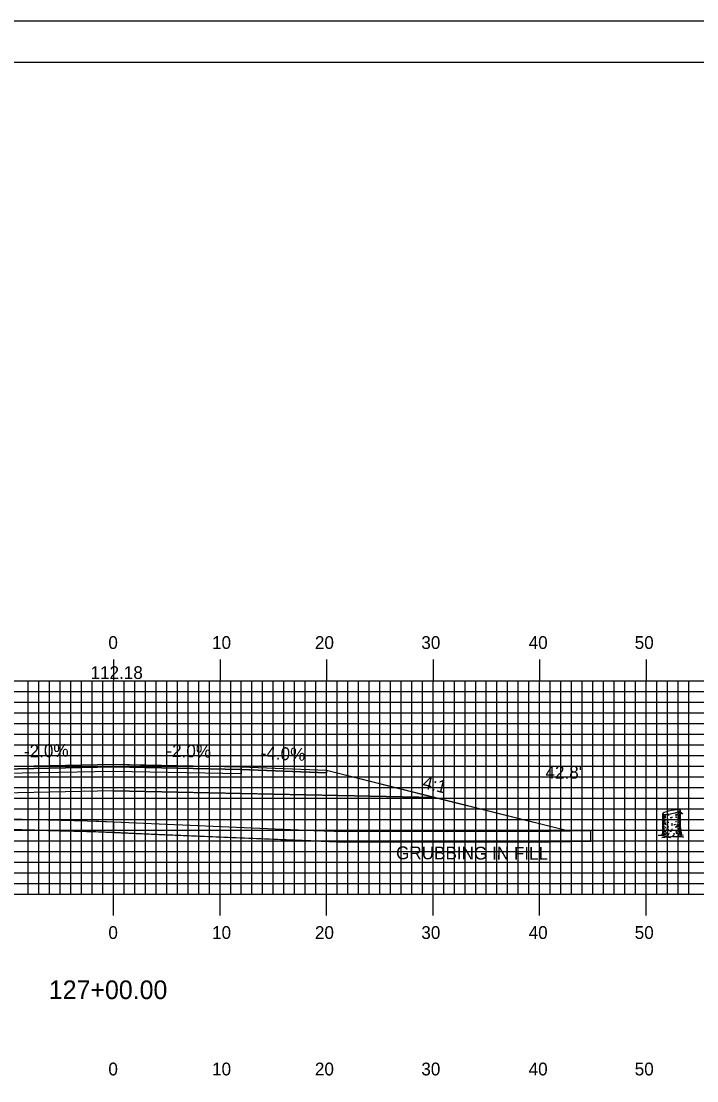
# Model space of a CAD drawing. Extents: x 1773203 to 1773546, y 442591 to 442811.
# Drawn here: x 1773360 to 1773423.4, y 442711.2 to 442810.5 of the extents above; entities that cross this region are included whole.
import ezdxf

# ---------------------------------------------------------------- set-up
doc = ezdxf.new("R2010")
doc.units = 0
for name, color, linetype in [('ANNOTATION', 7, 'Continuous'), ('BORDER', 7, 'Continuous'), ('D_Drainage_Culvert', 7, 'Continuous'), ('D_Roadway_Centerline', 7, 'Continuous'), ('D_Roadway_Centerline_Text', 7, 'Continuous'), ('D_Roadway_Edge_Shoulder', 7, 'Continuous'), ('D_Roadway_Edge_TW', 7, 'Continuous'), ('D_Roadway_Pavement', 7, 'Continuous'), ('D_Roadway_SubGrade', 7, 'Continuous'), ('D_Text_Standard', 7, 'Continuous'), ('GRUBBING IN FILL', 7, 'Continuous'), ('H_V ANNOTATION', 7, 'Continuous'), ('M_Trees_Conifer_Pay', 7, 'Continuous'), ('MAJOR', 7, 'Continuous'), ('MINOR', 7, 'Continuous'), ('PLOT BOUNDARY', 7, 'Continuous'), ('S_Roadway_Centerline', 7, 'Continuous')]:
    doc.layers.add(name, color=color, linetype=linetype)

msp = doc.modelspace()

# ---------------------------------------------------------------- linework, layer by layer
at = {"layer": 'BORDER'}
msp.add_lwpolyline([(1773219.033, 442596.665), (1773539.033, 442596.665), (1773539.033, 442806.665), (1773219.033, 442806.665)], close=True, dxfattribs=at)
at = {"layer": 'D_Drainage_Culvert'}
for p, q in [((1773380.633, 442740.604), (1773388.633, 442740.284)), ((1773368.632, 442738.344), (1773398.809, 442737.74))]:
    msp.add_line(p, q, dxfattribs=at)
msp.add_lwpolyline([(1773388.633, 442740.284), (1773392.633, 442739.284), (1773411.388, 442734.596)], dxfattribs=at)
at = {"layer": 'D_Roadway_Centerline'}
msp.add_lwpolyline([(1773327.807, 442736.112), (1773343.707, 442740.087), (1773348.633, 442740.284), (1773356.633, 442740.604), (1773368.632, 442740.844), (1773371.168, 442740.793), (1773380.633, 442740.604), (1773388.633, 442740.284), (1773388.633, 442740.284), (1773398.809, 442737.74), (1773411.388, 442734.596)], dxfattribs=at)
at = {"layer": 'D_Roadway_Edge_Shoulder'}
msp.add_lwpolyline([(1773380.633, 442740.604), (1773388.633, 442740.284), (1773388.633, 442740.034), (1773380.633, 442740.354)], close=True, dxfattribs=at)
at = {"layer": 'D_Roadway_Edge_TW'}
msp.add_lwpolyline([(1773356.632, 442740.354), (1773356.632, 442740.604), (1773368.632, 442740.844), (1773380.633, 442740.604), (1773380.633, 442740.354), (1773368.632, 442740.594)], close=True, dxfattribs=at)
at = {"layer": 'D_Roadway_Pavement'}
msp.add_lwpolyline([(1773356.632, 442739.937), (1773356.632, 442740.354), (1773368.632, 442740.594), (1773380.633, 442740.354), (1773380.633, 442739.937), (1773368.632, 442740.177)], close=True, dxfattribs=at)
at = {"layer": 'D_Roadway_SubGrade'}
msp.add_lwpolyline([(1773356.632, 442738.104), (1773333.959, 442737.65), (1773343.707, 442740.087), (1773343.707, 442739.829), (1773348.633, 442740.034), (1773356.632, 442740.354), (1773368.632, 442740.594), (1773380.633, 442740.354), (1773388.633, 442740.034), (1773388.633, 442740.034), (1773388.633, 442740.284), (1773398.809, 442737.74), (1773380.633, 442738.104), (1773368.632, 442738.344)], close=True, dxfattribs=at)
at = {"layer": 'GRUBBING IN FILL'}
msp.add_line((1773413.419, 442734.636), (1773413.419, 442733.636), dxfattribs=at)
msp.add_line((1773413.419, 442734.636), (1773413.419, 442733.636), dxfattribs=at)
for points in [[(1773323.846, 442736.25), (1773330.638, 442736.014), (1773339.301, 442735.713), (1773344.935, 442735.692), (1773349.428, 442735.77), (1773353.921, 442735.847), (1773360.04, 442735.698), (1773366.16, 442735.55), (1773368.633, 442735.449), (1773368.633, 442734.448), (1773366.13, 442734.55), (1773360.023, 442734.698), (1773353.917, 442734.846), (1773349.433, 442734.769), (1773343.621, 442734.682), (1773339.276, 442734.714), (1773331.561, 442734.981), (1773323.846, 442735.249)], [(1773323.846, 442736.25), (1773330.638, 442736.014), (1773339.301, 442735.713), (1773344.935, 442735.692), (1773349.428, 442735.77), (1773353.921, 442735.847), (1773360.04, 442735.698), (1773366.16, 442735.55), (1773368.633, 442735.449), (1773368.633, 442734.448), (1773366.13, 442734.55), (1773360.023, 442734.698), (1773353.917, 442734.846), (1773349.433, 442734.769), (1773343.621, 442734.682), (1773339.276, 442734.714), (1773331.561, 442734.981), (1773323.846, 442735.249)], [(1773368.633, 442735.449), (1773372.921, 442735.264), (1773380.188, 442734.957), (1773387.455, 442734.651), (1773388.889, 442734.593), (1773399.956, 442734.547), (1773409.589, 442734.56), (1773413.419, 442734.636), (1773413.419, 442733.636), (1773409.6, 442733.56), (1773399.951, 442733.547), (1773390.302, 442733.534), (1773380.146, 442733.958), (1773371.986, 442734.299), (1773368.633, 442734.448)], [(1773368.633, 442735.449), (1773372.921, 442735.264), (1773380.188, 442734.957), (1773387.455, 442734.651), (1773388.889, 442734.593), (1773399.956, 442734.547), (1773409.589, 442734.56), (1773413.419, 442734.636), (1773413.419, 442733.636), (1773409.6, 442733.56), (1773399.951, 442733.547), (1773390.302, 442733.534), (1773380.146, 442733.958), (1773371.986, 442734.299), (1773368.633, 442734.448)]]:
    msp.add_lwpolyline(points, close=True, dxfattribs=at)
msp.add_lwpolyline([(1773323.846, 442735.249), (1773339.276, 442734.714), (1773342.295, 442734.671), (1773344.948, 442734.693), (1773353.917, 442734.846), (1773366.13, 442734.55), (1773367.217, 442734.51), (1773372.878, 442734.265), (1773387.414, 442733.652), (1773390.302, 442733.534), (1773409.6, 442733.56), (1773413.419, 442733.636)], dxfattribs=at)
msp.add_lwpolyline([(1773323.846, 442735.249), (1773339.276, 442734.714), (1773342.295, 442734.671), (1773344.948, 442734.693), (1773353.917, 442734.846), (1773366.13, 442734.55), (1773367.217, 442734.51), (1773372.878, 442734.265), (1773387.414, 442733.652), (1773390.302, 442733.534), (1773409.6, 442733.56), (1773413.419, 442733.636)], dxfattribs=at)
at = {"layer": 'M_Trees_Conifer_Pay'}
for p, q in [((1773420.188, 442734.48), (1773420.188, 442736.202)), ((1773420.235, 442736.164), (1773420.235, 442735.693)), ((1773420.294, 442736.153), (1773420.294, 442736.055)), ((1773420.294, 442735.981), (1773420.294, 442735.777)), ((1773420.419, 442736.145), (1773420.419, 442735.913)), ((1773420.419, 442735.872), (1773420.419, 442735.798)), ((1773420.639, 442736.166), (1773420.639, 442735.998)), ((1773421.044, 442735.934), (1773421.044, 442735.839)), ((1773421.435, 442736.208), (1773421.435, 442736.008)), ((1773421.435, 442735.95), (1773421.435, 442735.862)), ((1773421.663, 442736.404), (1773421.663, 442736.181)), ((1773421.663, 442736.092), (1773421.663, 442736.045)), ((1773421.72, 442735.909), (1773421.669, 442735.849)), ((1773421.78, 442736.465), (1773421.78, 442736.302)), ((1773421.78, 442736.235), (1773421.78, 442736.107)), ((1773421.78, 442735.92), (1773421.78, 442735.584)), ((1773421.852, 442734.89), (1773421.852, 442736.537)), ((1773420.235, 442735.629), (1773420.235, 442735.321)), ((1773420.235, 442735.273), (1773420.235, 442734.781)), ((1773420.294, 442735.719), (1773420.294, 442735.52)), ((1773420.294, 442735.473), (1773420.294, 442735.137)), ((1773420.294, 442735.084), (1773420.294, 442734.948)), ((1773420.294, 442734.849), (1773420.294, 442734.47)), ((1773420.419, 442735.395), (1773420.419, 442735.256)), ((1773420.419, 442734.985), (1773420.419, 442734.843)), ((1773420.639, 442735.761), (1773420.639, 442735.524)), ((1773420.639, 442735.279), (1773420.639, 442735.127)), ((1773420.639, 442735.084), (1773420.639, 442734.91)), ((1773421.044, 442735.321), (1773421.044, 442735.246)), ((1773421.044, 442735.221), (1773421.044, 442735.073)), ((1773421.435, 442735.514), (1773421.435, 442735.409)), ((1773421.435, 442735.042), (1773421.435, 442734.896)), ((1773421.663, 442735.71), (1773421.663, 442735.578)), ((1773421.663, 442735.467), (1773421.663, 442735.357)), ((1773421.663, 442735.221), (1773421.663, 442735.08)), ((1773421.663, 442734.853), (1773421.663, 442734.68)), ((1773421.78, 442735.547), (1773421.78, 442735.384)), ((1773421.78, 442735.337), (1773421.78, 442735.12)), ((1773421.78, 442735.09), (1773421.78, 442735.015)), ((1773421.78, 442734.975), (1773421.78, 442734.802)), ((1773420.235, 442734.727), (1773420.235, 442734.48)), ((1773420.419, 442734.581), (1773420.419, 442734.487)), ((1773420.419, 442734.087), (1773420.582, 442734.151)), ((1773420.639, 442734.633), (1773420.639, 442734.48)), ((1773420.856, 442734.023), (1773420.73, 442734.087)), ((1773421.044, 442734.781), (1773421.044, 442734.628)), ((1773421.435, 442734.664), (1773421.435, 442734.575))]:
    msp.add_line(p, q, dxfattribs=at)
for points in [[(1773421.635, 442735.998), (1773421.605, 442735.913), (1773421.601, 442735.845), (1773421.631, 442735.782)], [(1773421.669, 442736.035), (1773421.706, 442735.961), (1773421.753, 442736.018), (1773421.811, 442736.086), (1773421.903, 442736.28), (1773421.967, 442736.327), (1773421.998, 442736.334)], [(1773421.683, 442735.782), (1773421.72, 442735.909), (1773421.784, 442736.025), (1773421.815, 442736.092), (1773421.883, 442736.239)], [(1773421.898, 442736.268), (1773421.973, 442736.276), (1773422.046, 442736.177)], [(1773421.852, 442734.89), (1773421.903, 442734.628), (1773421.92, 442734.355), (1773421.977, 442734.229), (1773422.113, 442734.199), (1773421.883, 442734.161), (1773421.883, 442734.161), (1773421.889, 442734.114), (1773422.136, 442734.019), (1773421.862, 442734.036), (1773421.506, 442734.056), (1773421.185, 442734.046), (1773421.191, 442734.128), (1773421.043, 442734.046), (1773420.856, 442734.023), (1773420.88, 442733.955), (1773420.612, 442733.998), (1773420.392, 442733.971), (1773420.099, 442733.989), (1773420.388, 442734.046), (1773420.419, 442734.087), (1773420.256, 442734.145), (1773420.019, 442734.155), (1773419.778, 442734.155), (1773420.12, 442734.213), (1773420.162, 442734.293), (1773420.188, 442734.48)], [(1773420.367, 442735.508), (1773420.361, 442735.603), (1773420.404, 442735.58), (1773420.404, 442735.485)], [(1773421.506, 442735.109), (1773421.519, 442735.032), (1773421.566, 442735.042), (1773421.553, 442735.209)], [(1773420.236, 442734.433), (1773420.215, 442734.355), (1773420.194, 442734.26)], [(1773420.314, 442734.412), (1773420.32, 442734.297), (1773420.267, 442734.208), (1773420.256, 442734.145)], [(1773420.477, 442734.439), (1773420.477, 442734.307), (1773420.388, 442734.208)], [(1773420.703, 442734.199), (1773420.771, 442734.293), (1773420.797, 442734.433)], [(1773421.191, 442734.128), (1773421.265, 442734.27), (1773421.275, 442734.371)], [(1773421.442, 442734.497), (1773421.452, 442734.371), (1773421.526, 442734.328)], [(1773421.72, 442734.108), (1773421.706, 442734.246), (1773421.631, 442734.375)], [(1773421.679, 442734.602), (1773421.753, 442734.497), (1773421.757, 442734.324), (1773421.883, 442734.161)], [(1773421.778, 442734.748), (1773421.784, 442734.602), (1773421.831, 442734.534), (1773421.841, 442734.334)]]:
    msp.add_lwpolyline(points, dxfattribs=at)
for centre, radius, start, end in [((1773420.22, 442736.024), 0.0334, 163.94846, 180), ((1773420.22, 442736.024), 0.0334, 180, 196.05154), ((1773420.219, 442736.201), 0.0314, 156.51582, 169.2194), ((1773420.214, 442736.201), 0.0264, 169.2194, 180.03145), ((1773420.211, 442736.201), 0.0226, 180.03145, 191.7194), ((1773420.211, 442736.201), 0.0226, 191.7194, 203.40735), ((1773420.23, 442736.026), 0.0441, 196.05154, 210), ((1773420.214, 442736.203), 0.0264, 203.40735, 214.2194), ((1773420.239, 442736.192), 0.0527, 146.7194, 156.51582), ((1773420.218, 442736.206), 0.0314, 214.2194, 226.92298), ((1773420.246, 442736.036), 0.0624, 210, 228.74941), ((1773420.263, 442736.176), 0.0817, 132.38868, 146.7194), ((1773420.233, 442736.221), 0.0527, 226.92298, 236.7194), ((1773420.249, 442736.246), 0.0817, 236.7194, 251.05013), ((1773420.319, 442736.118), 0.172, 228.74941, 240), ((1773420.377, 442736.051), 0.251, 124.2194, 132.38868), ((1773420.304, 442736.405), 0.251, 251.05013, 259.2194), ((1773420.518, 442736.463), 0.571, 240, 240.33672), ((1773420.687, 442735.596), 0.802, 108.05939, 124.2194), ((1773420.407, 442736.947), 0.802, 259.2194, 275.37941), ((1773420.518, 442736.463), 0.571, 246.85973, 257.98457), ((1773422.044, 442731.434), 5.179, 101.7194, 108.05939), ((1773419.996, 442741.305), 5.179, 275.37941, 281.7194), ((1773421.02, 442740.214), 4.124, 264.6955, 266.73309), ((1773421.019, 442739.981), 4.124, 268.07512, 270), ((1773422.044, 442731.434), 5.179, 95.37941, 101.7194), ((1773421.019, 442739.981), 4.124, 270, 270.35814), ((1773419.996, 442741.305), 5.179, 281.7194, 288.05939), ((1773421.019, 442739.981), 4.124, 275.78493, 277.05584), ((1773421.02, 442740.214), 4.124, 276.23804, 278.1032), ((1773421.633, 442735.792), 0.802, 79.2194, 95.37941), ((1773421.521, 442736.696), 0.571, 278.1032, 284.36665), ((1773421.353, 442737.143), 0.802, 288.05939, 304.2194), ((1773421.521, 442736.851), 0.571, 284.43166, 292.41325), ((1773421.521, 442736.696), 0.571, 297.0237, 300), ((1773421.736, 442736.333), 0.251, 71.05013, 79.2194), ((1773421.663, 442736.687), 0.251, 304.2194, 312.38868), ((1773421.72, 442736.506), 0.172, 300, 311.25059), ((1773421.72, 442736.351), 0.172, 300, 311.25059), ((1773421.791, 442736.493), 0.0817, 56.7194, 71.05013), ((1773421.777, 442736.563), 0.0817, 312.38868, 326.7194), ((1773421.793, 442736.423), 0.0624, 311.25059, 330), ((1773421.793, 442736.269), 0.0624, 311.25059, 330), ((1773421.807, 442736.517), 0.0527, 46.92298, 56.7194), ((1773421.822, 442736.533), 0.0314, 34.2194, 46.92298), ((1773421.801, 442736.547), 0.0527, 326.7194, 336.51582), ((1773421.808, 442736.414), 0.0441, 330, 343.94846), ((1773421.808, 442736.259), 0.0441, 330, 343.94846), ((1773421.826, 442736.536), 0.0264, 23.40735, 34.2194), ((1773421.829, 442736.537), 0.0226, 11.7194, 23.40735), ((1773421.821, 442736.538), 0.0314, 336.51582, 349.2194), ((1773421.819, 442736.411), 0.0334, 343.94846, 354.21506), ((1773421.819, 442736.256), 0.0334, 343.94846, 354.21506), ((1773421.829, 442736.537), 0.0226, 0.03145, 11.7194), ((1773421.826, 442736.537), 0.0264, 349.2194, 0.03145), ((1773420.22, 442735.577), 0.0334, 163.94846, 180), ((1773420.22, 442735.577), 0.0334, 180, 196.05154), ((1773420.22, 442735.367), 0.0334, 163.94846, 180), ((1773420.22, 442735.367), 0.0334, 180, 196.05154), ((1773420.22, 442735.13), 0.0334, 163.94846, 180), ((1773420.22, 442735.13), 0.0334, 180, 196.05154), ((1773420.22, 442734.932), 0.0334, 163.94846, 180), ((1773420.23, 442735.58), 0.0441, 196.05154, 210), ((1773420.23, 442735.37), 0.0441, 196.05154, 210), ((1773420.23, 442735.133), 0.0441, 196.05154, 210), ((1773420.246, 442735.589), 0.0624, 210, 228.74941), ((1773420.246, 442735.379), 0.0624, 210, 228.74941), ((1773420.246, 442735.142), 0.0624, 210, 228.74941), ((1773420.319, 442735.671), 0.172, 228.74941, 240), ((1773420.319, 442735.461), 0.172, 228.74941, 240), ((1773420.319, 442735.225), 0.172, 228.74941, 240), ((1773420.518, 442736.017), 0.571, 240, 240.33672), ((1773420.518, 442735.806), 0.571, 240, 246.85973), ((1773420.518, 442735.57), 0.571, 240, 246.85973), ((1773420.507, 442735.378), 0.571, 241.23686, 248.02677), ((1773420.519, 442736.252), 0.571, 240, 247.05866), ((1773420.518, 442735.806), 0.571, 259.27072, 261.8968), ((1773421.019, 442739.324), 4.124, 261.8968, 263.14738), ((1773421.019, 442739.534), 4.124, 264.08098, 266.66759), ((1773421.019, 442739.087), 4.124, 264.71603, 266.31934), ((1773421.019, 442739.324), 4.124, 270, 270.35814), ((1773421.019, 442739.324), 4.124, 273.14934, 275.45691), ((1773421.02, 442739.77), 4.124, 273.70524, 275.95043), ((1773421.019, 442739.534), 4.124, 277.61247, 278.1032), ((1773421.52, 442736.017), 0.571, 278.1032, 286.92962), ((1773421.521, 442736.252), 0.571, 284.44928, 297.04285), ((1773421.52, 442735.57), 0.571, 285.39827, 297.18959), ((1773421.52, 442735.372), 0.571, 289.29072, 300), ((1773421.52, 442736.017), 0.571, 297.18959, 300), ((1773421.52, 442735.806), 0.571, 297.18959, 300), ((1773421.719, 442735.671), 0.172, 300, 311.25059), ((1773421.719, 442735.461), 0.172, 300, 311.25059), ((1773421.719, 442735.027), 0.172, 300, 311.25059), ((1773421.791, 442735.589), 0.0624, 311.25059, 330), ((1773421.791, 442735.379), 0.0624, 311.25059, 330), ((1773421.791, 442734.944), 0.0624, 311.25059, 330), ((1773421.807, 442735.58), 0.0441, 330, 343.94846), ((1773421.807, 442735.37), 0.0441, 330, 343.94846), ((1773421.807, 442734.935), 0.0441, 330, 343.94846), ((1773421.817, 442735.577), 0.0334, 343.94846, 354.21506), ((1773421.817, 442735.367), 0.0334, 343.94846, 354.21506), ((1773421.817, 442734.932), 0.0334, 343.94846, 354.21506), ((1773421.819, 442735.812), 0.0334, 343.94846, 354.21506), ((1773420.22, 442734.737), 0.0334, 163.94846, 180), ((1773420.22, 442734.737), 0.0334, 180, 196.05154), ((1773420.22, 442734.516), 0.0334, 163.94846, 180), ((1773420.22, 442734.516), 0.0334, 180, 196.05154), ((1773420.23, 442734.74), 0.0441, 196.05154, 210), ((1773420.23, 442734.519), 0.0441, 196.05154, 210), ((1773420.246, 442734.749), 0.0624, 210, 228.74941), ((1773420.246, 442734.528), 0.0624, 210, 228.74941), ((1773420.319, 442734.831), 0.172, 228.74941, 240), ((1773420.319, 442734.611), 0.172, 228.74941, 240), ((1773420.518, 442735.176), 0.571, 240, 246.85973), ((1773420.518, 442734.956), 0.571, 240, 244.53138), ((1773421.019, 442738.474), 4.124, 262.44379, 263.51202), ((1773421.019, 442738.89), 4.124, 263.49906, 265.83975), ((1773421.019, 442738.694), 4.124, 267.81166, 270), ((1773421.019, 442738.694), 4.124, 270, 270.13279), ((1773421.019, 442738.694), 4.124, 275.78493, 276.78961), ((1773421.019, 442738.474), 4.124, 277.36842, 278.1032), ((1773421.52, 442734.956), 0.571, 278.1032, 281.63703), ((1773421.52, 442735.176), 0.571, 288.50673, 297.27208), ((1773421.719, 442734.611), 0.172, 300, 311.25059), ((1773421.791, 442734.528), 0.0624, 311.25059, 330), ((1773421.807, 442734.519), 0.0441, 330, 343.94846), ((1773421.817, 442734.516), 0.0334, 343.94846, 354.21506)]:
    msp.add_arc(centre, radius, start, end, dxfattribs=at)
at = {"layer": 'MAJOR'}
for p, q in [((1773368.633, 442750.669), (1773368.633, 442748.665)), ((1773378.633, 442750.669), (1773378.633, 442748.665)), ((1773388.633, 442750.669), (1773388.633, 442748.665)), ((1773398.633, 442750.669), (1773398.633, 442748.665)), ((1773408.633, 442750.669), (1773408.633, 442748.665)), ((1773418.633, 442750.669), (1773418.633, 442748.665)), ((1773228.633, 442748.665), (1773508.633, 442748.665)), ((1773228.633, 442748.665), (1773508.633, 442748.665)), ((1773368.633, 442728.665), (1773368.633, 442748.665)), ((1773378.633, 442728.665), (1773378.633, 442748.665)), ((1773388.633, 442728.665), (1773388.633, 442748.665)), ((1773398.633, 442728.665), (1773398.633, 442748.665)), ((1773408.633, 442728.665), (1773408.633, 442748.665)), ((1773418.633, 442728.665), (1773418.633, 442748.665)), ((1773228.633, 442743.665), (1773508.633, 442743.665)), ((1773228.633, 442738.665), (1773508.633, 442738.665)), ((1773228.633, 442733.665), (1773508.633, 442733.665)), ((1773228.633, 442728.665), (1773508.633, 442728.665)), ((1773228.633, 442728.665), (1773508.633, 442728.665)), ((1773368.633, 442726.661), (1773368.633, 442728.665)), ((1773378.633, 442726.661), (1773378.633, 442728.665)), ((1773388.633, 442726.661), (1773388.633, 442728.665)), ((1773398.633, 442726.661), (1773398.633, 442728.665)), ((1773408.633, 442726.661), (1773408.633, 442728.665)), ((1773418.633, 442726.661), (1773418.633, 442728.665))]:
    msp.add_line(p, q, dxfattribs=at)
at = {"layer": 'MINOR'}
for p, q in [((1773360.633, 442728.665), (1773360.633, 442748.665)), ((1773361.633, 442728.665), (1773361.633, 442748.665)), ((1773362.633, 442728.665), (1773362.633, 442748.665)), ((1773363.633, 442728.665), (1773363.633, 442748.665)), ((1773364.633, 442728.665), (1773364.633, 442748.665)), ((1773365.633, 442728.665), (1773365.633, 442748.665)), ((1773366.633, 442728.665), (1773366.633, 442748.665)), ((1773367.633, 442728.665), (1773367.633, 442748.665)), ((1773369.633, 442728.665), (1773369.633, 442748.665)), ((1773370.633, 442728.665), (1773370.633, 442748.665)), ((1773371.633, 442728.665), (1773371.633, 442748.665)), ((1773372.633, 442728.665), (1773372.633, 442748.665)), ((1773373.633, 442728.665), (1773373.633, 442748.665)), ((1773374.633, 442728.665), (1773374.633, 442748.665)), ((1773375.633, 442728.665), (1773375.633, 442748.665)), ((1773376.633, 442728.665), (1773376.633, 442748.665)), ((1773377.633, 442728.665), (1773377.633, 442748.665)), ((1773379.633, 442728.665), (1773379.633, 442748.665)), ((1773380.633, 442728.665), (1773380.633, 442748.665)), ((1773381.633, 442728.665), (1773381.633, 442748.665)), ((1773382.633, 442728.665), (1773382.633, 442748.665)), ((1773383.633, 442728.665), (1773383.633, 442748.665)), ((1773384.633, 442728.665), (1773384.633, 442748.665)), ((1773385.633, 442728.665), (1773385.633, 442748.665)), ((1773386.633, 442728.665), (1773386.633, 442748.665)), ((1773387.633, 442728.665), (1773387.633, 442748.665)), ((1773389.633, 442728.665), (1773389.633, 442748.665)), ((1773390.633, 442728.665), (1773390.633, 442748.665)), ((1773391.633, 442728.665), (1773391.633, 442748.665)), ((1773392.633, 442728.665), (1773392.633, 442748.665)), ((1773393.633, 442728.665), (1773393.633, 442748.665)), ((1773394.633, 442728.665), (1773394.633, 442748.665)), ((1773395.633, 442728.665), (1773395.633, 442748.665)), ((1773396.633, 442728.665), (1773396.633, 442748.665)), ((1773397.633, 442728.665), (1773397.633, 442748.665)), ((1773399.633, 442728.665), (1773399.633, 442748.665)), ((1773400.633, 442728.665), (1773400.633, 442748.665)), ((1773401.633, 442728.665), (1773401.633, 442748.665)), ((1773402.633, 442728.665), (1773402.633, 442748.665)), ((1773403.633, 442728.665), (1773403.633, 442748.665)), ((1773404.633, 442728.665), (1773404.633, 442748.665)), ((1773405.633, 442728.665), (1773405.633, 442748.665)), ((1773406.633, 442728.665), (1773406.633, 442748.665)), ((1773407.633, 442728.665), (1773407.633, 442748.665)), ((1773409.633, 442728.665), (1773409.633, 442748.665)), ((1773410.633, 442728.665), (1773410.633, 442748.665)), ((1773411.633, 442728.665), (1773411.633, 442748.665)), ((1773412.633, 442728.665), (1773412.633, 442748.665)), ((1773413.633, 442728.665), (1773413.633, 442748.665)), ((1773414.633, 442728.665), (1773414.633, 442748.665)), ((1773415.633, 442728.665), (1773415.633, 442748.665)), ((1773416.633, 442728.665), (1773416.633, 442748.665)), ((1773417.633, 442728.665), (1773417.633, 442748.665)), ((1773419.633, 442728.665), (1773419.633, 442748.665)), ((1773420.633, 442728.665), (1773420.633, 442748.665)), ((1773421.633, 442728.665), (1773421.633, 442748.665)), ((1773422.633, 442728.665), (1773422.633, 442748.665)), ((1773228.633, 442747.665), (1773508.633, 442747.665)), ((1773228.633, 442746.665), (1773508.633, 442746.665)), ((1773228.633, 442745.665), (1773508.633, 442745.665)), ((1773228.633, 442744.665), (1773508.633, 442744.665)), ((1773228.633, 442742.665), (1773508.633, 442742.665)), ((1773228.633, 442741.665), (1773508.633, 442741.665)), ((1773228.633, 442740.665), (1773508.633, 442740.665)), ((1773228.633, 442739.665), (1773508.633, 442739.665)), ((1773228.633, 442737.665), (1773508.633, 442737.665)), ((1773228.633, 442736.665), (1773508.633, 442736.665)), ((1773228.633, 442735.665), (1773508.633, 442735.665)), ((1773228.633, 442734.665), (1773508.633, 442734.665)), ((1773228.633, 442732.665), (1773508.633, 442732.665)), ((1773228.633, 442731.665), (1773508.633, 442731.665)), ((1773228.633, 442730.665), (1773508.633, 442730.665)), ((1773228.633, 442729.665), (1773508.633, 442729.665))]:
    msp.add_line(p, q, dxfattribs=at)
at = {"layer": 'PLOT BOUNDARY'}
msp.add_lwpolyline([(1773202.846, 442590.547), (1773542.846, 442590.547), (1773542.846, 442810.547), (1773202.846, 442810.547)], close=True, dxfattribs=at)
at = {"layer": 'S_Roadway_Centerline'}
msp.add_lwpolyline([(1773300.463, 442736.972), (1773315.371, 442736.594), (1773319.046, 442736.474), (1773321.975, 442736.315), (1773339.301, 442735.713), (1773342.298, 442735.671), (1773344.935, 442735.692), (1773353.921, 442735.847), (1773366.16, 442735.55), (1773367.257, 442735.509), (1773372.921, 442735.264), (1773387.455, 442734.651), (1773390.322, 442734.534), (1773409.589, 442734.56), (1773414.673, 442734.661), (1773430.964, 442734.646)], dxfattribs=at)

# ---------------------------------------------------------------- texts
at = {"layer": 'ANNOTATION'}
for s, rotation, p in [('-2.0%', 1.14579, (1773360.239, 442741.477)), ('-2.0%', 358.85435, (1773373.587, 442741.546)), ('-4.0%', 357.70927, (1773382.425, 442741.334)), ('4:1', 345.96263, (1773397.566, 442738.636))]:
    msp.add_text(s, height=1.2, rotation=rotation, dxfattribs=at).set_placement(p)
at = {"layer": 'D_Roadway_Centerline'}
for s, p in [('C', (1773368.627, 442740.844)), ('L', (1773368.632, 442740.837))]:
    msp.add_text(s, height=0.0146, dxfattribs=at).set_placement(p)
at = {"layer": 'D_Roadway_Centerline_Text'}
msp.add_text('112.18', height=1.2, dxfattribs=at).set_placement((1773366.477, 442748.848))
at = {"layer": 'D_Text_Standard'}
msp.add_text("42.8'", height=1.2, dxfattribs=at).set_placement((1773409.183, 442739.501))
at = {"layer": 'GRUBBING IN FILL'}
msp.add_text('GRUBBING IN FILL', height=1.2, rotation=359.81456, dxfattribs=at).set_placement((1773395.16, 442731.941))
at = {"layer": 'H_V ANNOTATION'}
for s, height, p in [('0', 1.2, (1773368.151, 442751.665)), ('10', 1.2, (1773377.884, 442751.665)), ('20', 1.2, (1773387.541, 442751.665)), ('30', 1.2, (1773397.53, 442751.665)), ('40', 1.2, (1773407.605, 442751.665)), ('50', 1.2, (1773417.562, 442751.665)), ('0', 1.2, (1773368.151, 442724.465)), ('10', 1.2, (1773377.884, 442724.465)), ('20', 1.2, (1773387.541, 442724.465)), ('30', 1.2, (1773397.53, 442724.465)), ('40', 1.2, (1773407.605, 442724.465)), ('50', 1.2, (1773417.562, 442724.465)), ('127+00.00', 1.75, (1773362.562, 442718.821)), ('0', 1.2, (1773368.151, 442711.665)), ('10', 1.2, (1773377.884, 442711.665)), ('20', 1.2, (1773387.541, 442711.665)), ('30', 1.2, (1773397.53, 442711.665)), ('40', 1.2, (1773407.605, 442711.665)), ('50', 1.2, (1773417.562, 442711.665))]:
    msp.add_text(s, height=height, dxfattribs=at).set_placement(p)

doc.saveas('drawing.dxf')
